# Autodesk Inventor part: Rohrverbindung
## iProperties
Company: alltrotec GmbH
Shininess: 64.0
Length Units: 11269
Angle Units: 11279
Time Units: 11290
Mass Units: 11283
Length Display Precision: 3
Angle Display Precision: 2
Compacted: True
Document SubType Name: Modeling
Created: 2003-01
Material: Stahl (schweißbar)
Designer: R.Lampe
Catalog Web Link: http://www.alltrotec.de
Part Number: Rohrverbindung
Cost Center: 2,304 kg
Authority: 293155,4 mm^3
Description: T-Stück DN65 45°
Density: 0.0
Volumn: 0.0
Area: 0.0
PropertySet Name: Model Information
Control State: 0
Master: False
Checked Out: False
Masse: 2,304 kg
SaveDate: 2003-01-16
SaveTime: 23:28
TotalMass: 2,304 kg
TotalVolume: 293155,4 mm^3
Author: R.Lampe
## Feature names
1. Extrusion3
2. Extrusion4
3. Rundung1 [Fillet]
4. Rundung2 [Fillet]
